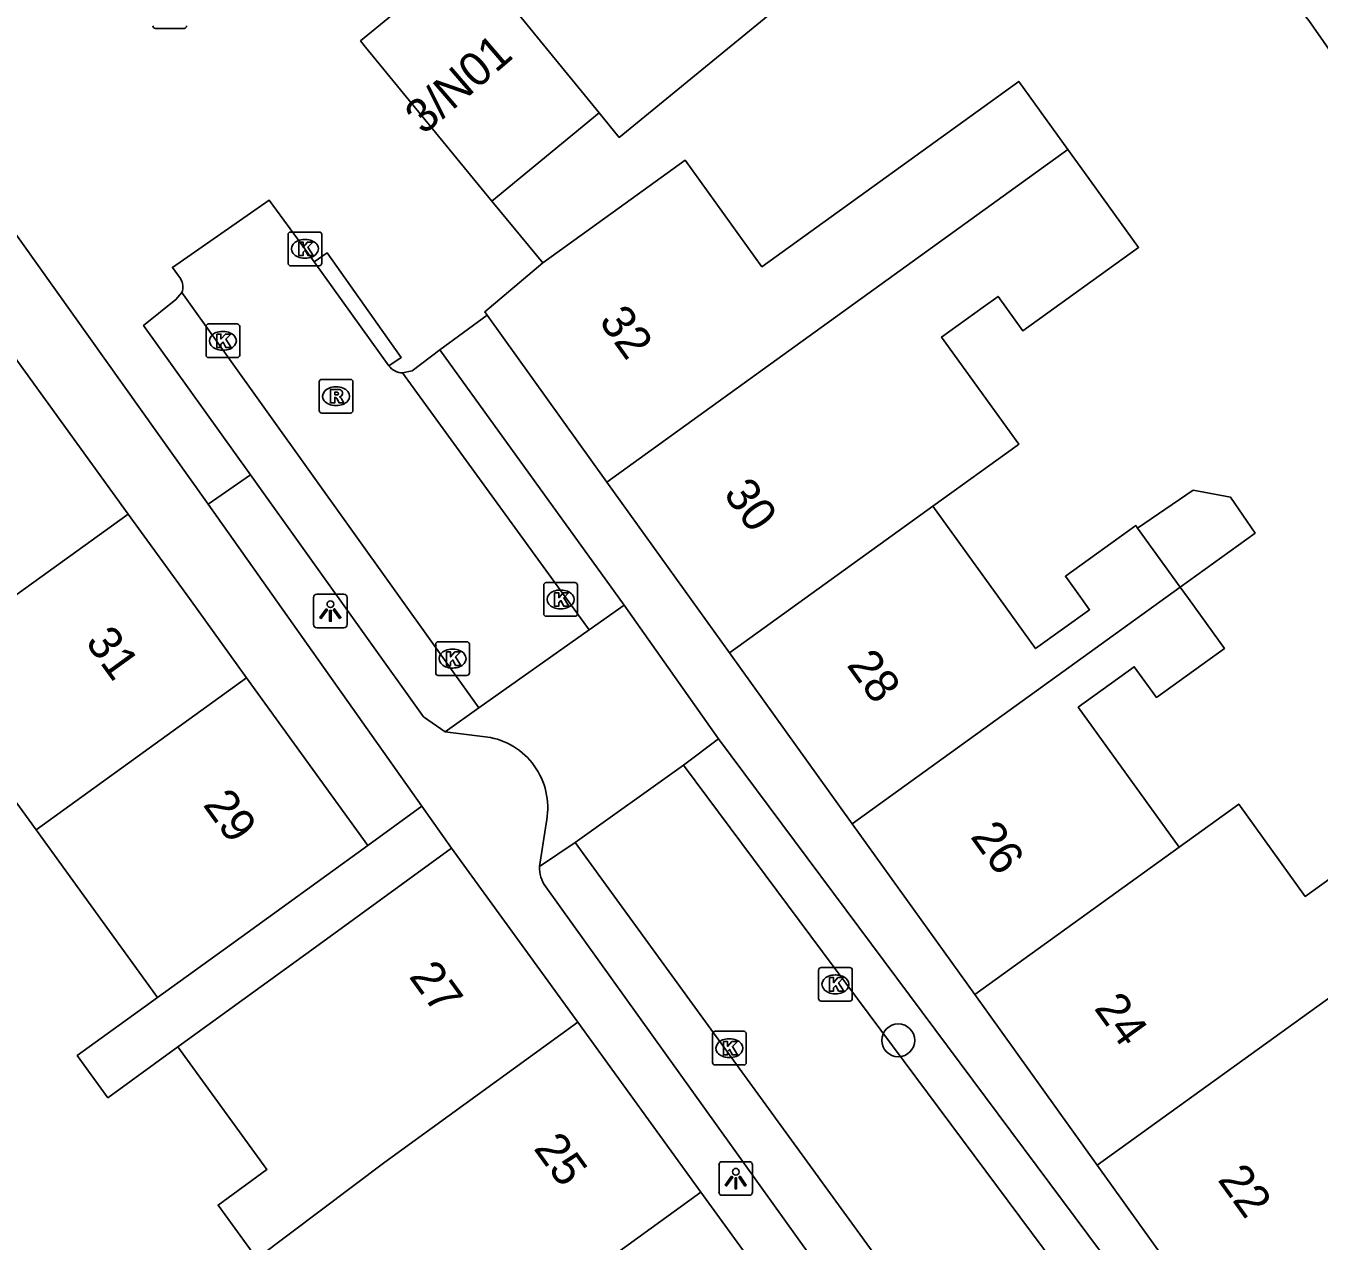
# Model space of a CAD drawing. Extents: x 161882 to 162509, y 381687 to 382379.
# Drawn here: x 162139.15 to 162177.57, y 381980.92 to 382017.01 of the extents above; entities that cross this region are included whole.
import ezdxf

# ---------------------------------------------------------------- set-up
doc = ezdxf.new("R2010")
doc.units = 0
for name, color, linetype in [('IMGEO_Boom', 7, 'Continuous'), ('IMGEO_Kolk', 7, 'Continuous'), ('IMGEO_Lichtpunt', 7, 'Continuous'), ('IMGEO_Pand', 7, 'Continuous'), ('IMGEO_Pand_nummerreeks', 7, 'Continuous'), ('IMGEO_Parkeervlak_open', 7, 'Continuous'), ('IMGEO_Rijbaan_lokaal_open', 7, 'Continuous'), ('IMGEO_Rioolput', 7, 'Continuous'), ('IMGEO_Voetpad_open', 7, 'Continuous'), ('IMGEO_Woonerf_open', 7, 'Continuous')]:
    doc.layers.add(name, color=color, linetype=linetype)

msp = doc.modelspace()

# ---------------------------------------------------------------- linework, layer by layer
at = {"layer": 'IMGEO_Boom'}
msp.add_circle((162165.072, 381986.882), 0.489, dxfattribs=at)
at = {"layer": 'IMGEO_Kolk'}
for p, q in [((162143.855, 382016.938), (162143.003, 382016.938)), ((162146.944, 382009.963), (162146.944, 382010.815)), ((162147.019, 382010.889), (162147.871, 382010.889)), ((162147.432, 382010.669), (162147.457, 382010.669)), ((162147.945, 382010.815), (162147.945, 382009.963)), ((162147.871, 382009.889), (162147.019, 382009.889)), ((162147.455, 382010.109), (162147.43, 382010.109)), ((162144.507, 382007.232), (162144.507, 382008.084)), ((162144.582, 382008.158), (162145.434, 382008.158)), ((162144.995, 382007.938), (162145.02, 382007.938)), ((162145.508, 382008.084), (162145.508, 382007.232)), ((162145.434, 382007.158), (162144.582, 382007.158)), ((162145.018, 382007.378), (162144.993, 382007.378)), ((162154.54, 381999.551), (162154.54, 382000.403)), ((162154.615, 382000.477), (162155.467, 382000.477)), ((162155.028, 382000.257), (162155.053, 382000.257)), ((162155.541, 382000.403), (162155.541, 381999.551)), ((162155.467, 381999.477), (162154.615, 381999.477)), ((162155.051, 381999.697), (162155.026, 381999.697)), ((162151.404, 381998.719), (162152.256, 381998.719)), ((162151.329, 381997.793), (162151.329, 381998.645)), ((162151.817, 381998.499), (162151.842, 381998.499)), ((162152.33, 381998.645), (162152.33, 381997.793)), ((162151.84, 381997.939), (162151.815, 381997.939)), ((162152.256, 381997.719), (162151.404, 381997.719)), ((162162.705, 381988.119), (162162.705, 381988.971)), ((162162.78, 381989.045), (162163.632, 381989.045)), ((162163.193, 381988.825), (162163.218, 381988.825)), ((162163.706, 381988.971), (162163.706, 381988.119)), ((162163.632, 381988.045), (162162.78, 381988.045)), ((162163.216, 381988.265), (162163.191, 381988.265)), ((162159.554, 381986.224), (162159.554, 381987.076)), ((162159.629, 381987.15), (162160.481, 381987.15)), ((162160.042, 381986.93), (162160.067, 381986.93)), ((162160.555, 381987.076), (162160.555, 381986.224)), ((162160.481, 381986.15), (162159.629, 381986.15)), ((162160.065, 381986.37), (162160.04, 381986.37))]:
    msp.add_line(p, q, dxfattribs=at)
for points in [[(162143.855, 382016.938), (162143.003, 382016.938)], [(162146.944, 382009.963), (162146.944, 382010.815)], [(162147.019, 382010.889), (162147.871, 382010.889)], [(162147.265, 382010.589), (162147.388, 382010.589), (162147.388, 382010.438), (162147.518, 382010.589), (162147.682, 382010.589), (162147.536, 382010.438), (162147.689, 382010.189), (162147.537, 382010.189), (162147.452, 382010.353), (162147.388, 382010.286), (162147.388, 382010.189), (162147.265, 382010.189), (162147.265, 382010.589)], [(162147.945, 382010.815), (162147.945, 382009.963)], [(162147.871, 382009.889), (162147.019, 382009.889)], [(162144.507, 382007.232), (162144.507, 382008.084)], [(162144.582, 382008.158), (162145.434, 382008.158)], [(162145.508, 382008.084), (162145.508, 382007.232)], [(162144.828, 382007.858), (162144.951, 382007.858), (162144.951, 382007.707), (162145.081, 382007.858), (162145.245, 382007.858), (162145.099, 382007.707), (162145.252, 382007.458), (162145.1, 382007.458), (162145.015, 382007.622), (162144.951, 382007.555), (162144.951, 382007.458), (162144.828, 382007.458), (162144.828, 382007.858)], [(162145.434, 382007.158), (162144.582, 382007.158)], [(162154.54, 381999.551), (162154.54, 382000.403)], [(162154.615, 382000.477), (162155.467, 382000.477)], [(162155.541, 382000.403), (162155.541, 381999.551)], [(162154.861, 382000.177), (162154.984, 382000.177), (162154.984, 382000.026), (162155.114, 382000.177), (162155.278, 382000.177), (162155.132, 382000.026), (162155.285, 381999.777), (162155.133, 381999.777), (162155.048, 381999.941), (162154.984, 381999.874), (162154.984, 381999.777), (162154.861, 381999.777), (162154.861, 382000.177)], [(162155.467, 381999.477), (162154.615, 381999.477)], [(162151.404, 381998.719), (162152.256, 381998.719)], [(162151.329, 381997.793), (162151.329, 381998.645)], [(162151.65, 381998.419), (162151.773, 381998.419), (162151.773, 381998.268), (162151.903, 381998.419), (162152.067, 381998.419), (162151.921, 381998.268), (162152.074, 381998.019), (162151.922, 381998.019), (162151.837, 381998.183), (162151.773, 381998.116), (162151.773, 381998.019), (162151.65, 381998.019), (162151.65, 381998.419)], [(162152.33, 381998.645), (162152.33, 381997.793)], [(162152.256, 381997.719), (162151.404, 381997.719)], [(162162.705, 381988.119), (162162.705, 381988.971)], [(162162.78, 381989.045), (162163.632, 381989.045)], [(162163.026, 381988.745), (162163.149, 381988.745), (162163.149, 381988.594), (162163.279, 381988.745), (162163.443, 381988.745), (162163.297, 381988.594), (162163.45, 381988.345), (162163.298, 381988.345), (162163.213, 381988.509), (162163.149, 381988.442), (162163.149, 381988.345), (162163.026, 381988.345), (162163.026, 381988.745)], [(162163.706, 381988.971), (162163.706, 381988.119)], [(162163.632, 381988.045), (162162.78, 381988.045)], [(162159.554, 381986.224), (162159.554, 381987.076)], [(162159.629, 381987.15), (162160.481, 381987.15)], [(162159.875, 381986.85), (162159.998, 381986.85), (162159.998, 381986.699), (162160.128, 381986.85), (162160.292, 381986.85), (162160.146, 381986.699), (162160.299, 381986.45), (162160.147, 381986.45), (162160.062, 381986.614), (162159.998, 381986.547), (162159.998, 381986.45), (162159.875, 381986.45), (162159.875, 381986.85)], [(162160.555, 381987.076), (162160.555, 381986.224)], [(162160.481, 381986.15), (162159.629, 381986.15)]]:
    msp.add_lwpolyline(points, dxfattribs=at)
for centre, start, end in [((162143.005, 382017.014), 181.552, 268.448), ((162143.005, 382017.014), 181.552, 268.448), ((162143.853, 382017.014), 271.552, 358.448), ((162143.853, 382017.014), 271.552, 358.448), ((162147.021, 382010.813), 91.552, 178.448), ((162147.021, 382010.813), 91.552, 178.448), ((162147.869, 382010.813), 1.552, 88.448), ((162147.869, 382010.813), 1.552, 88.448), ((162147.021, 382009.965), 181.552, 268.448), ((162147.021, 382009.965), 181.552, 268.448), ((162147.869, 382009.965), 271.552, 358.448), ((162147.869, 382009.965), 271.552, 358.448), ((162144.584, 382008.082), 91.552, 178.448), ((162144.584, 382008.082), 91.552, 178.448), ((162145.432, 382008.082), 1.552, 88.448), ((162145.432, 382008.082), 1.552, 88.448), ((162144.584, 382007.234), 181.552, 268.448), ((162144.584, 382007.234), 181.552, 268.448), ((162145.432, 382007.234), 271.552, 358.448), ((162145.432, 382007.234), 271.552, 358.448), ((162154.617, 382000.401), 91.552, 178.448), ((162154.617, 382000.401), 91.552, 178.448), ((162155.465, 382000.401), 1.552, 88.448), ((162155.465, 382000.401), 1.552, 88.448), ((162154.617, 381999.553), 181.552, 268.448), ((162154.617, 381999.553), 181.552, 268.448), ((162155.465, 381999.553), 271.552, 358.448), ((162155.465, 381999.553), 271.552, 358.448), ((162151.406, 381998.643), 91.552, 178.448), ((162151.406, 381998.643), 91.552, 178.448), ((162152.254, 381998.643), 1.552, 88.448), ((162152.254, 381998.643), 1.552, 88.448), ((162151.406, 381997.795), 181.552, 268.448), ((162151.406, 381997.795), 181.552, 268.448), ((162152.254, 381997.795), 271.552, 358.448), ((162152.254, 381997.795), 271.552, 358.448), ((162162.782, 381988.969), 91.552, 178.448), ((162162.782, 381988.969), 91.552, 178.448), ((162163.63, 381988.969), 1.552, 88.448), ((162163.63, 381988.969), 1.552, 88.448), ((162162.782, 381988.121), 181.552, 268.448), ((162162.782, 381988.121), 181.552, 268.448), ((162163.63, 381988.121), 271.552, 358.448), ((162163.63, 381988.121), 271.552, 358.448), ((162159.631, 381987.074), 91.552, 178.448), ((162159.631, 381987.074), 91.552, 178.448), ((162160.479, 381987.074), 1.552, 88.448), ((162160.479, 381987.074), 1.552, 88.448), ((162159.631, 381986.226), 181.552, 268.448), ((162159.631, 381986.226), 181.552, 268.448), ((162160.479, 381986.226), 271.552, 358.448), ((162160.479, 381986.226), 271.552, 358.448)]:
    msp.add_arc(centre, 0.0765, start, end, dxfattribs=at)
for centre, major_axis, ratio, start_param, end_param in [((162147.431, 382010.389), (-0.387, 0.002), 0.722429, 4.712389, 7.853982), ((162147.456, 382010.389), (-0.39, 0.002), 0.717154, 1.570796, 4.712389), ((162144.994, 382007.658), (-0.387, 0.002), 0.722429, 4.712389, 7.853982), ((162145.019, 382007.658), (-0.39, 0.002), 0.717154, 1.570796, 4.712389), ((162155.027, 381999.977), (-0.387, 0.002), 0.722429, 4.712389, 7.853982), ((162155.052, 381999.977), (-0.39, 0.002), 0.717154, 1.570796, 4.712389), ((162151.816, 381998.219), (-0.387, 0.002), 0.722429, 4.712389, 7.853982), ((162151.841, 381998.219), (-0.39, 0.002), 0.717154, 1.570796, 4.712389), ((162163.192, 381988.545), (-0.387, 0.002), 0.722429, 4.712389, 7.853982), ((162163.217, 381988.545), (-0.39, 0.002), 0.717154, 1.570796, 4.712389), ((162160.041, 381986.65), (-0.387, 0.002), 0.722429, 4.712389, 7.853982), ((162160.066, 381986.65), (-0.39, 0.002), 0.717154, 1.570796, 4.712389)]:
    msp.add_ellipse(centre, major_axis=major_axis, ratio=ratio, start_param=start_param, end_param=end_param, dxfattribs=at)
at = {"layer": 'IMGEO_Lichtpunt'}
for p, q in [((162147.702, 382000.036), (162147.702, 381999.229)), ((162147.702, 382000.036), (162147.702, 381999.229)), ((162148.604, 382000.131), (162147.796, 382000.131)), ((162148.604, 382000.131), (162147.796, 382000.131)), ((162148.698, 381999.229), (162148.698, 382000.036)), ((162148.698, 381999.229), (162148.698, 382000.036)), ((162147.796, 381999.135), (162148.604, 381999.135)), ((162147.796, 381999.135), (162148.604, 381999.135)), ((162159.746, 381983.182), (162159.746, 381982.375)), ((162159.746, 381983.182), (162159.746, 381982.375)), ((162160.648, 381983.277), (162159.84, 381983.277)), ((162160.648, 381983.277), (162159.84, 381983.277)), ((162160.742, 381982.375), (162160.742, 381983.182)), ((162160.742, 381982.375), (162160.742, 381983.182)), ((162159.84, 381982.281), (162160.648, 381982.281)), ((162159.84, 381982.281), (162160.648, 381982.281))]:
    msp.add_line(p, q, dxfattribs=at)
for points in [[(162148.076, 381999.7), (162148.115, 381999.672), (162147.927, 381999.41), (162147.889, 381999.437), (162148.076, 381999.7)], [(162148.178, 381999.652), (162148.225, 381999.652), (162148.225, 381999.33), (162148.178, 381999.33), (162148.178, 381999.652)], [(162148.288, 381999.672), (162148.326, 381999.699), (162148.513, 381999.437), (162148.474, 381999.409), (162148.288, 381999.672)], [(162160.12, 381982.846), (162160.159, 381982.818), (162159.971, 381982.556), (162159.933, 381982.583), (162160.12, 381982.846)], [(162160.222, 381982.798), (162160.269, 381982.798), (162160.269, 381982.476), (162160.222, 381982.476), (162160.222, 381982.798)], [(162160.332, 381982.818), (162160.37, 381982.845), (162160.557, 381982.583), (162160.518, 381982.555), (162160.332, 381982.818)]]:
    msp.add_lwpolyline(points, dxfattribs=at)
for centre in [(162148.201, 381999.834), (162160.245, 381982.98)]:
    msp.add_circle(centre, 0.0994, dxfattribs=at)
for centre, start, end in [((162147.796, 382000.036), 90, 180), ((162147.796, 382000.036), 90, 180), ((162148.604, 382000.036), 0, 90), ((162148.604, 382000.036), 0, 90), ((162147.796, 381999.229), 180, 270), ((162147.796, 381999.229), 180, 270), ((162148.604, 381999.229), 270, 0), ((162148.604, 381999.229), 270, 360), ((162159.84, 381983.182), 90, 180), ((162159.84, 381983.182), 90, 180), ((162160.648, 381983.182), 0, 90), ((162160.648, 381983.182), 0, 90), ((162159.84, 381982.375), 180, 270), ((162159.84, 381982.375), 180, 270), ((162160.648, 381982.375), 270, 0), ((162160.648, 381982.375), 270, 360)]:
    msp.add_arc(centre, 0.0946, start, end, dxfattribs=at)
at = {"layer": 'IMGEO_Pand'}
for points in [[(162193.718, 382027.859), (162192.868, 382027.162), (162178.511, 382015.397), (162177.271, 382017.167), (162176.155, 382018.528), (162176.553, 382018.855), (162171.139, 382025.462), (162160.651, 382016.868), (162156.783, 382013.698), (162156.187, 382014.426)], [(162156.187, 382014.426), (162154.446, 382016.562), (162152.462, 382018.996)], [(162152.994, 382011.81), (162149.249, 382016.379), (162149.098, 382016.563), (162150.019, 382017.317)], [(162154.512, 382009.975), (162156.782, 382011.612), (162158.736, 382013.022), (162161.02, 382009.857), (162168.653, 382015.361), (162170.113, 382013.339)], [(162156.187, 382014.426), (162152.994, 382011.81)], [(162156.417, 382003.461), (162166.091, 382010.438), (162170.113, 382013.339)], [(162170.113, 382013.339), (162170.608, 382012.653), (162172.211, 382010.431), (162168.775, 382007.953), (162168.035, 382008.978), (162167.594, 382008.66), (162166.358, 382007.768), (162168.653, 382004.587), (162168.599, 382004.548), (162166.1, 382002.746)], [(162152.854, 382008.424), (162152.786, 382008.518), (162154.512, 382009.975)], [(162156.417, 382003.461), (162152.854, 382008.424)], [(162142.196, 382002.512), (162138.679, 382007.373)], [(162160.059, 381998.389), (162156.417, 382003.461)], [(162173.446, 382000.342), (162175.673, 382001.948), (162174.942, 382003.014), (162173.829, 382003.221), (162172.183, 382002.092)], [(162166.1, 382002.746), (162162.292, 382000), (162160.059, 381998.389)], [(162166.1, 382002.746), (162168.081, 382000), (162169.152, 381998.516), (162170.755, 381999.673), (162170.519, 382000), (162170.039, 382000.665), (162172.126, 382002.171), (162172.183, 382002.092)], [(162135.939, 381997.989), (162138.721, 382000), (162142.196, 382002.512)], [(162145.711, 381997.652), (162144.013, 382000), (162142.196, 382002.512)], [(162172.183, 382002.092), (162173.446, 382000.342)], [(162163.701, 381993.316), (162173.446, 382000.342)], [(162173.446, 382000.342), (162173.693, 382000), (162174.76, 381998.521), (162172.741, 381997.065), (162172.082, 381997.978), (162170.417, 381996.776), (162173.415, 381992.621)], [(162160.059, 381998.389), (162163.701, 381993.316)], [(162139.459, 381993.132), (162135.939, 381997.989)], [(162145.711, 381997.652), (162139.459, 381993.132)], [(162149.316, 381992.669), (162145.711, 381997.652)], [(162173.415, 381992.621), (162175.186, 381993.898), (162177.164, 381991.155), (162180.657, 381993.673), (162182.33, 381991.35)], [(162167.342, 381988.244), (162163.701, 381993.316)], [(162143.067, 381988.153), (162139.459, 381993.132)], [(162149.316, 381992.669), (162145.264, 381989.741), (162143.067, 381988.153)], [(162143.669, 381986.685), (162147.756, 381989.651), (162151.802, 381992.587)], [(162151.802, 381992.587), (162155.55, 381987.421)], [(162173.415, 381992.621), (162167.342, 381988.244)], [(162182.33, 381991.35), (162170.985, 381983.17)], [(162170.985, 381983.17), (162167.342, 381988.244)], [(162155.55, 381987.421), (162149.823, 381983.266), (162146.018, 381980.399)], [(162155.55, 381987.421), (162159.209, 381982.377)], [(162146.018, 381980.399), (162144.863, 381981.99), (162146.312, 381983.042), (162143.669, 381986.685)], [(162174.716, 381977.972), (162170.985, 381983.17)], [(162159.209, 381982.377), (162153.482, 381978.221), (162153.215, 381978.026)], [(162159.209, 381982.377), (162162.869, 381977.333)]]:
    msp.add_lwpolyline(points, dxfattribs=at)
at = {"layer": 'IMGEO_Parkeervlak_open'}
for points in [[(162145.827, 382003.676), (162142.653, 382008.114), (162143.611, 382008.881), (162143.791, 382009.095)], [(162150.348, 382006.704), (162150.627, 382006.768), (162151.457, 382007.393)]]:
    msp.add_lwpolyline(points, dxfattribs=at)
at = {"layer": 'IMGEO_Rijbaan_lokaal_open'}
for points in [[(162143.744, 382009.505), (162143.506, 382009.84), (162146.38, 382011.84), (162147.445, 382010.389), (162147.719, 382010.003)], [(162147.719, 382010.003), (162149.938, 382006.916)], [(162143.791, 382009.095), (162152.615, 381996.754)], [(162155.893, 381999.072), (162150.348, 382006.704)], [(162156.925, 381999.802), (162155.893, 381999.072)], [(162156.925, 381999.802), (162159.734, 381995.833)], [(162155.893, 381999.072), (162152.615, 381996.754)], [(162152.615, 381996.754), (162151.61, 381996.043)], [(162152.959, 381995.876), (162151.61, 381996.043)], [(162158.69, 381995.058), (162159.734, 381995.833)], [(162155.477, 381992.759), (162158.69, 381995.058)], [(162170.763, 381978.853), (162158.69, 381995.058)], [(162154.41, 381992.049), (162154.607, 381993.326)], [(162155.477, 381992.759), (162154.41, 381992.049)], [(162167.325, 381976.452), (162155.477, 381992.759)]]:
    msp.add_lwpolyline(points, dxfattribs=at)
for centre, radius, start, end in [((162143.385, 382009.256), 0.437, 338.3298, 34.7492), ((162150.367, 382007.243), 0.539, 217.3169, 267.9986), ((162152.532, 381993.792), 2.127, 347.3385, 78.4086)]:
    msp.add_arc(centre, radius, start, end, dxfattribs=at)
at = {"layer": 'IMGEO_Rioolput'}
for p, q in [((162147.869, 382005.587), (162147.869, 382006.439)), ((162147.944, 382006.513), (162148.796, 382006.513)), ((162148.87, 382006.439), (162148.87, 382005.587)), ((162148.357, 382006.293), (162148.382, 382006.293)), ((162148.38, 382005.733), (162148.355, 382005.733)), ((162148.796, 382005.513), (162147.944, 382005.513))]:
    msp.add_line(p, q, dxfattribs=at)
for points in [[(162147.869, 382005.587), (162147.869, 382006.439)], [(162147.944, 382006.513), (162148.796, 382006.513)], [(162148.87, 382006.439), (162148.87, 382005.587)], [(162148.458, 382006.211), (162148.206, 382006.213), (162148.206, 382005.813)], [(162148.384, 382006.132), (162148.33, 382006.132), (162148.33, 382006.051)], [(162148.33, 382006.051), (162148.382, 382006.051)], [(162148.206, 382005.813), (162148.33, 382005.813), (162148.33, 382005.975), (162148.341, 382005.975)], [(162148.388, 382005.946), (162148.459, 382005.813), (162148.599, 382005.813), (162148.534, 382005.939)], [(162148.796, 382005.513), (162147.944, 382005.513)]]:
    msp.add_lwpolyline(points, dxfattribs=at)
for centre, radius, start, end in [((162147.946, 382006.437), 0.0765, 91.552, 178.448), ((162147.946, 382006.437), 0.0765, 91.552, 178.448), ((162148.794, 382006.437), 0.0765, 1.552, 88.448), ((162148.794, 382006.437), 0.0765, 1.552, 88.448), ((162148.366, 382006.24), 0.19, 274.7715, 282.9687), ((162148.39, 382006.036), 0.0964, 77.0061, 93.1865), ((162148.404, 382006.093), 0.0378, 276.6634, 79.6772), ((162148.457, 382006.101), 0.109, 350.3612, 89.416), ((162148.455, 382006.101), 0.112, 277.5842, 350.9817), ((162148.439, 382005.886), 0.108, 29.5134, 73.7905), ((162148.34, 382005.922), 0.0533, 26.0293, 88.6989), ((162147.946, 382005.589), 0.0765, 181.552, 268.448), ((162147.946, 382005.589), 0.0765, 181.552, 268.448), ((162148.794, 382005.589), 0.0765, 271.552, 358.448), ((162148.794, 382005.589), 0.0765, 271.552, 358.448)]:
    msp.add_arc(centre, radius, start, end, dxfattribs=at)
for centre, major_axis, ratio, start_param, end_param in [((162148.356, 382006.013), (-0.387, 0.002), 0.722429, 4.712389, 7.853982), ((162148.381, 382006.013), (-0.39, 0.002), 0.717154, 1.570796, 4.712389)]:
    msp.add_ellipse(centre, major_axis=major_axis, ratio=ratio, start_param=start_param, end_param=end_param, dxfattribs=at)
at = {"layer": 'IMGEO_Voetpad_open'}
for points in [[(162147.719, 382010.003), (162148.105, 382010.273), (162150.308, 382007.166), (162149.938, 382006.916)], [(162151.457, 382007.393), (162152.854, 382008.424)], [(162151.457, 382007.393), (162156.925, 381999.802)], [(162144.573, 382002.81), (162145.827, 382003.676)], [(162151.61, 381996.043), (162150.965, 381996.491), (162145.827, 382003.676)], [(162144.573, 382002.81), (162150.92, 381993.835)], [(162159.734, 381995.833), (162171.83, 381979.598)], [(162150.92, 381993.835), (162149.316, 381992.669)], [(162150.92, 381993.835), (162151.802, 381992.587)], [(162166.011, 381975.535), (162154.599, 381991.442)], [(162143.669, 381986.685), (162141.59, 381985.176), (162140.681, 381986.429), (162143.067, 381988.153)]]:
    msp.add_lwpolyline(points, dxfattribs=at)
msp.add_arc((162155.428, 381992.033), 1.018, 179.0947, 215.495, dxfattribs=at)
at = {"layer": 'IMGEO_Woonerf_open'}
for points in [[(162137.504, 382012.714), (162144.573, 382002.81)], [(162152.994, 382011.81), (162154.512, 382009.975)]]:
    msp.add_lwpolyline(points, dxfattribs=at)

# ---------------------------------------------------------------- texts
at = {"layer": 'IMGEO_Pand_nummerreeks'}
for s, rotation, p in [('3/N01', 40.7087, (162150.968, 382013.753)), ('32', 305.7925, (162156.157, 382008.24)), ('30', 305.7925, (162159.856, 382003.108)), ('31', 305.8816, (162140.9, 381998.707)), ('28', 305.7867, (162163.519, 381998.026)), ('29', 305.8816, (162144.394, 381993.877)), ('26', 305.7872, (162167.193, 381992.931)), ('27', 305.9601, (162150.514, 381988.776)), ('24', 305.7872, (162170.867, 381987.834)), ('25', 305.9601, (162154.217, 381983.671)), ('22', 305.7872, (162174.539, 381982.74))]:
    msp.add_text(s, height=1, rotation=rotation, dxfattribs=at).set_placement(p)

doc.saveas('drawing.dxf')
